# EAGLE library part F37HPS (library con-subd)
SUB-D
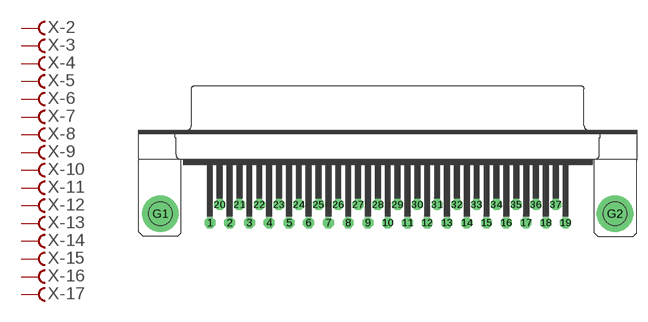
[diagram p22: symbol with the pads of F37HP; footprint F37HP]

Designator prefix X; gates -2=F -3=F -4=F -5=F -6=F -7=F -8=F -9=F -10=F -11=F -12=F -13=F -14=F -15=F -16=F -17=F -18=F -19=F -20=F -21=F -22=F -23=F -24=F -25=F -26=F -27=F -28=F -29=F -30=F -31=F -32=F -33=F -34=F -35=F -36=F -37=F -G=GND -1=FV

## F37HPS (OC_FARNELL: unknown; OC_NEWARK: unknown)  [F37HP]
1  -1:F  pas
2  -2:F  pas
3  -3:F  pas
4  -4:F  pas
5  -5:F  pas
6  -6:F  pas
7  -7:F  pas
8  -8:F  pas
9  -9:F  pas
10  -10:F  pas
11  -11:F  pas
12  -12:F  pas
13  -13:F  pas
14  -14:F  pas
15  -15:F  pas
16  -16:F  pas
17  -17:F  pas
18  -18:F  pas
19  -19:F  pas
20  -20:F  pas
21  -21:F  pas
22  -22:F  pas
23  -23:F  pas
24  -24:F  pas
25  -25:F  pas
26  -26:F  pas
27  -27:F  pas
28  -28:F  pas
29  -29:F  pas
30  -30:F  pas
31  -31:F  pas
32  -32:F  pas
33  -33:F  pas
34  -34:F  pas
35  -35:F  pas
36  -36:F  pas
37  -37:F  pas
G1  -G:G1  pas
G2  -G:G2  pas

## Footprint F37HP (pad centres in mm)
SUB-D
drill 1.016 octagon: 1 -24.841,-1.27; 2 -22.073,-1.27; 3 -19.329,-1.27; 4 -16.561,-1.27; 5 -13.792,-1.27; 6 -11.049,-1.27; 7 -8.28,-1.27; 8 -5.512,-1.27; 9 -2.769,-1.27; 10 0,-1.27; 11 2.769,-1.27; 12 5.512,-1.27; 13 8.28,-1.27; 14 11.049,-1.27; 15 13.818,-1.27; 16 16.561,-1.27; 17 19.329,-1.27; 18 22.098,-1.27; 19 24.841,-1.27; 20 -23.47,1.27; 21 -20.701,1.27; 22 -17.932,1.27; 23 -15.189,1.27; 24 -12.421,1.27; 25 -9.652,1.27; 26 -6.909,1.27; 27 -4.14,1.27; 28 -1.372,1.27; 29 1.372,1.27; 30 4.14,1.27; 31 6.909,1.27; 32 9.677,1.27; 33 12.421,1.27; 34 15.189,1.27; 35 17.958,1.27; 36 20.701,1.27; 37 23.47,1.27
drill 3.302 pad 5.08 round: G1 -31.75,0; G2 31.75,0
